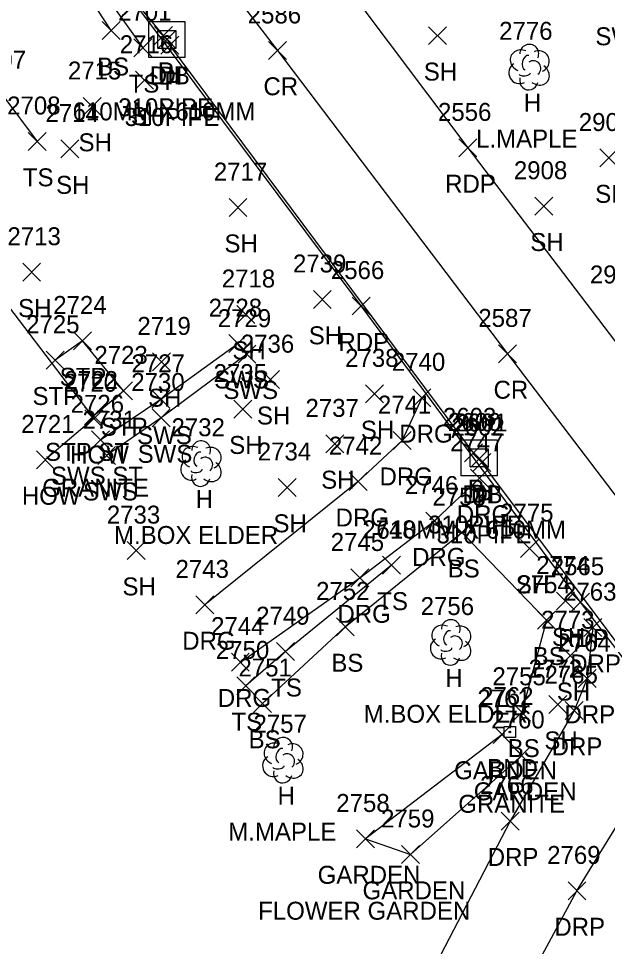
# Model space of a CAD drawing. Extents: x 1634209 to 1639641, y 608564 to 612258.
# Drawn here: x 1639264.6 to 1639330.2, y 610967 to 611070.4 of the extents above; entities that cross this region are included whole.
import ezdxf

# ---------------------------------------------------------------- set-up
doc = ezdxf.new("R2010")
doc.units = 0
for name, color, linetype in [('D_A', 7, 'Continuous'), ('D_C', 7, 'Continuous'), ('D_I', 7, 'Continuous'), ('D_TIC', 7, 'Continuous'), ('DCP', 7, 'Continuous'), ('DS', 7, 'Continuous'), ('L_A', 7, 'Continuous'), ('L_C', 7, 'Continuous'), ('L_I', 7, 'Continuous'), ('L_TIC', 7, 'Continuous'), ('LAPB', 7, 'Continuous'), ('LBC', 7, 'Continuous'), ('LBF', 7, 'Continuous'), ('LELB', 7, 'Continuous'), ('LTD', 7, 'Continuous'), ('M_A', 7, 'Continuous'), ('M_C', 7, 'Continuous'), ('M_I', 7, 'Continuous'), ('MHBP', 7, 'Continuous'), ('P_A', 7, 'Continuous'), ('P_I', 7, 'Continuous'), ('P_TIC', 7, 'Continuous'), ('PET', 7, 'Continuous'), ('PRC', 7, 'Continuous'), ('R_A', 7, 'Continuous'), ('R_I', 7, 'Continuous'), ('R_TIC', 7, 'Continuous'), ('RDG', 7, 'Continuous'), ('RDP', 7, 'Continuous'), ('RSW', 7, 'Continuous')]:
    doc.layers.add(name, color=color, linetype=linetype)

msp = doc.modelspace()

# ---------------------------------------------------------------- linework, layer by layer
at = {"layer": 'D_TIC'}
for points in [[(1639279.74, 611067.51), (1639281.74, 611069.51)], [(1639281.74, 611067.51), (1639279.74, 611069.51)], [(1639280.12, 611067.06), (1639282.12, 611069.06)], [(1639282.12, 611067.06), (1639280.12, 611069.06)], [(1639280.46, 611066.43), (1639282.46, 611068.43)], [(1639282.46, 611066.43), (1639280.46, 611068.43)], [(1639314.26, 611021.03), (1639316.26, 611023.03)], [(1639316.26, 611021.03), (1639314.26, 611023.03)], [(1639314.94, 611020.4), (1639316.94, 611022.4)], [(1639316.94, 611020.4), (1639314.94, 611022.4)], [(1639315.2, 611019.93), (1639317.2, 611021.93)], [(1639317.2, 611019.93), (1639315.2, 611021.93)]]:
    msp.add_lwpolyline(points, dxfattribs=at)
at = {"layer": 'DCP'}
for points in [[(1639280.74, 611068.51), (1639160.8, 611213.26)], [(1639315.26, 611022.03), (1639281.46, 611067.43)], [(1639346.24, 610980.85), (1639316.2, 611020.93)]]:
    msp.add_lwpolyline(points, dxfattribs=at)
at = {"layer": 'DS'}
for p, q in [((1639279.12, 611070.05), (1639283.12, 611070.05)), ((1639279.12, 611066.05), (1639279.12, 611070.05)), ((1639283.12, 611070.05), (1639283.12, 611066.05)), ((1639280.12, 611067.05), (1639280.12, 611069.05)), ((1639280.12, 611069.05), (1639282.12, 611069.05)), ((1639282.12, 611069.05), (1639282.12, 611067.05)), ((1639281.12, 611068.05), (1639281.12, 611068.05)), ((1639281.12, 611068.05), (1639281.12, 611068.05)), ((1639282.12, 611067.05), (1639280.12, 611067.05)), ((1639283.12, 611066.05), (1639279.12, 611066.05)), ((1639313.9, 611023.46), (1639317.9, 611023.46)), ((1639313.9, 611019.46), (1639313.9, 611023.46)), ((1639317.9, 611023.46), (1639317.9, 611019.46)), ((1639314.9, 611020.46), (1639314.9, 611022.46)), ((1639314.9, 611022.46), (1639316.9, 611022.46)), ((1639316.9, 611022.46), (1639316.9, 611020.46)), ((1639315.91, 611021.46), (1639315.91, 611021.46)), ((1639315.91, 611021.46), (1639315.91, 611021.46)), ((1639316.9, 611020.46), (1639314.9, 611020.46)), ((1639317.9, 611019.46), (1639313.9, 611019.46))]:
    msp.add_line(p, q, dxfattribs=at)
at = {"layer": 'L_TIC'}
for points in [[(1639273.91, 611068.05), (1639275.91, 611070.05)], [(1639275.91, 611068.05), (1639273.91, 611070.05)], [(1639310.26, 611067.49), (1639312.26, 611069.49)], [(1639312.26, 611067.49), (1639310.26, 611069.49)], [(1639277.46, 611066.15), (1639279.46, 611068.15)], [(1639279.46, 611066.15), (1639277.46, 611068.15)], [(1639277.63, 611062.53), (1639279.63, 611064.53)], [(1639279.63, 611062.53), (1639277.63, 611064.53)], [(1639271.8, 611059.61), (1639273.8, 611061.61)], [(1639273.8, 611059.61), (1639271.8, 611061.61)], [(1639265.68, 611055.71), (1639267.68, 611057.71)], [(1639267.68, 611055.71), (1639265.68, 611057.71)], [(1639269.31, 611054.87), (1639271.31, 611056.87)], [(1639271.31, 611054.87), (1639269.31, 611056.87)], [(1639329.34, 611053.87), (1639331.34, 611055.87)], [(1639331.34, 611053.87), (1639329.34, 611055.87)], [(1639288.05, 611048.35), (1639290.05, 611050.35)], [(1639290.05, 611048.35), (1639288.05, 611050.35)], [(1639322.11, 611048.5), (1639324.11, 611050.5)], [(1639324.11, 611048.5), (1639322.11, 611050.5)], [(1639265.07, 611041.15), (1639267.07, 611043.15)], [(1639267.07, 611041.15), (1639265.07, 611043.15)], [(1639297.44, 611038.11), (1639299.44, 611040.11)], [(1639299.44, 611038.11), (1639297.44, 611040.11)], [(1639288.93, 611036.44), (1639290.93, 611038.44)], [(1639290.93, 611036.44), (1639288.93, 611038.44)], [(1639270.73, 611033.49), (1639272.73, 611035.49)], [(1639272.73, 611033.49), (1639270.73, 611035.49)], [(1639267.7, 611031.35), (1639269.7, 611033.35)], [(1639269.7, 611031.35), (1639267.7, 611033.35)], [(1639279.54, 611031.16), (1639281.54, 611033.16)], [(1639281.54, 611031.16), (1639279.54, 611033.16)], [(1639291.67, 611029.18), (1639293.67, 611031.18)], [(1639293.67, 611029.18), (1639291.67, 611031.18)], [(1639275.31, 611027.93), (1639277.31, 611029.93)], [(1639277.31, 611027.93), (1639275.31, 611029.93)], [(1639303.24, 611027.6), (1639305.24, 611029.6)], [(1639305.24, 611027.6), (1639303.24, 611029.6)], [(1639288.59, 611025.9), (1639290.59, 611027.9)], [(1639290.59, 611025.9), (1639288.59, 611027.9)], [(1639271.97, 611025.13), (1639273.97, 611027.13)], [(1639273.97, 611025.13), (1639271.97, 611027.13)], [(1639271.98, 611024.83), (1639273.98, 611026.83)], [(1639273.98, 611024.83), (1639271.98, 611026.83)], [(1639298.82, 611022.03), (1639300.82, 611024.03)], [(1639300.82, 611022.03), (1639298.82, 611024.03)], [(1639266.59, 611020.24), (1639268.59, 611022.24)], [(1639268.59, 611020.24), (1639266.59, 611022.24)], [(1639293.51, 611017.17), (1639295.51, 611019.17)], [(1639295.51, 611017.17), (1639293.51, 611019.17)], [(1639312.96, 611012.14), (1639314.96, 611014.14)], [(1639314.96, 611012.14), (1639312.96, 611014.14)], [(1639276.7, 611010.14), (1639278.7, 611012.14)], [(1639278.7, 611010.14), (1639276.7, 611012.14)], [(1639320.5, 611010.37), (1639322.5, 611012.37)], [(1639322.5, 611010.37), (1639320.5, 611012.37)], [(1639305.15, 611008.5), (1639307.15, 611010.5)], [(1639307.15, 611008.5), (1639305.15, 611010.5)], [(1639324.52, 611004.52), (1639326.52, 611006.52)], [(1639326.52, 611004.52), (1639324.52, 611006.52)], [(1639300, 611001.64), (1639302, 611003.64)], [(1639302, 611001.64), (1639300, 611003.64)], [(1639322.42, 611002.39), (1639324.42, 611004.39)], [(1639324.42, 611002.39), (1639322.42, 611004.39)], [(1639293.34, 610998.88), (1639295.34, 611000.88)], [(1639295.34, 610998.88), (1639293.34, 611000.88)], [(1639325.06, 610998.43), (1639327.06, 611000.43)], [(1639327.06, 610998.43), (1639325.06, 611000.43)], [(1639288.92, 610995.07), (1639290.92, 610997.07)], [(1639290.92, 610995.07), (1639288.92, 610997.07)], [(1639290.79, 610993.11), (1639292.79, 610995.11)], [(1639292.79, 610993.11), (1639290.79, 610995.11)], [(1639323.68, 610992.99), (1639325.68, 610994.99)], [(1639325.68, 610992.99), (1639323.68, 610994.99)], [(1639319.64, 610992.13), (1639321.64, 610994.13)], [(1639321.64, 610992.13), (1639319.64, 610994.13)], [(1639317.45, 610989.66), (1639319.45, 610991.66)], [(1639319.45, 610989.66), (1639317.45, 610991.66)], [(1639319.64, 610987.32), (1639321.64, 610989.32)], [(1639321.64, 610987.32), (1639319.64, 610989.32)], [(1639302.25, 610978.02), (1639304.25, 610980.02)], [(1639304.25, 610978.02), (1639302.25, 610980.02)], [(1639307.25, 610976.29), (1639309.25, 610978.29)], [(1639309.25, 610976.29), (1639307.25, 610978.29)]]:
    msp.add_lwpolyline(points, dxfattribs=at)
at = {"layer": 'LAPB'}
for points in [[(1639303.25, 610979.02), (1639308.25, 610977.29), (1639320.64, 610988.32), (1639318.45, 610990.66)], [(1639318.45, 610990.66), (1639303.25, 610979.02)]]:
    msp.add_lwpolyline(points, dxfattribs=at)
at = {"layer": 'LBC'}
msp.add_lwpolyline([(1639253.26, 611038.19), (1639259.87, 611042.99), (1639272.98, 611025.83), (1639267.59, 611021.24)], dxfattribs=at)
at = {"layer": 'LBF'}
msp.add_lwpolyline([(1639272.97, 611026.13), (1639276.31, 611028.93), (1639271.73, 611034.49), (1639268.7, 611032.35)], dxfattribs=at)
at = {"layer": 'LELB'}
for points in [[(1639268.88, 611080.56), (1639278.46, 611067.15)], [(1639274.91, 611069.05), (1639268.28, 611079.25)], [(1639249.48, 611049.96), (1639262.84, 611061.82), (1639266.68, 611056.71)], [(1639291.79, 610994.11), (1639301, 611002.64), (1639313.96, 611013.14), (1639323.42, 611003.39), (1639320.64, 610993.13)], [(1639306.15, 611009.5), (1639294.34, 610999.88), (1639289.92, 610996.07)]]:
    msp.add_lwpolyline(points, dxfattribs=at)
at = {"layer": 'LTD'}
for p, q in [((1639321.45, 611065.03), (1639321.45, 611065.03)), ((1639321.45, 611065.03), (1639321.45, 611065.03)), ((1639284.9, 611020.87), (1639284.9, 611020.87)), ((1639284.9, 611020.87), (1639284.9, 611020.87)), ((1639312.71, 611000.95), (1639312.71, 611000.95)), ((1639312.71, 611000.95), (1639312.71, 611000.95)), ((1639294.03, 610987.84), (1639294.03, 610987.84)), ((1639294.03, 610987.84), (1639294.03, 610987.84))]:
    msp.add_line(p, q, dxfattribs=at)
for centre in [(1639321.49, 611066.47), (1639284.95, 611022.3), (1639312.75, 611002.39), (1639294.07, 610989.27)]:
    msp.add_arc(centre, 1.05, 335.5272, 180.9563, dxfattribs=at)
for centre, major_axis, ratio, start_param, end_param in [((1639320.66, 611065.7), (1.21, -0.51), 0.895232, 1.570796, 4.712389), ((1639322.49, 611065.62), (-1.14, -0.48), 0.949671, 1.570796, 4.712389), ((1639321.24, 611065.49), (-0.208, -0.792), 0.645439, 3.141593, 6.283185), ((1639321.95, 611064.87), (-0.5, 0.667), 0.989748, 3.141593, 6.283185), ((1639320.36, 611064.32), (0.58, -1.04), 0.959034, 3.141593, 6.283185), ((1639322.45, 611064.2), (-1.09, 0.79), 0.841452, 1.570796, 4.712389), ((1639321.45, 611063.53), (0.26, 1.06), 0.942809, 1.570796, 4.712389), ((1639320.99, 611064.28), (-0.625, -0.083), 0.423636, 0, 3.141593), ((1639284.11, 611021.53), (1.21, -0.51), 0.895232, 1.570796, 4.712389), ((1639284.69, 611021.32), (-0.208, -0.792), 0.645439, 3.141593, 6.283185), ((1639285.94, 611021.45), (-1.14, -0.48), 0.949671, 1.570796, 4.712389), ((1639283.82, 611020.16), (0.58, -1.04), 0.959034, 3.141593, 6.283185), ((1639285.4, 611020.7), (-0.5, 0.667), 0.989748, 3.141593, 6.283185), ((1639284.44, 611020.11), (-0.625, -0.083), 0.423636, 0, 3.141593), ((1639285.9, 611020.03), (-1.09, 0.79), 0.841452, 1.570796, 4.712389), ((1639284.9, 611019.37), (0.26, 1.06), 0.942809, 1.570796, 4.712389), ((1639311.92, 611001.62), (1.21, -0.51), 0.895232, 1.570796, 4.712389), ((1639313.75, 611001.54), (-1.14, -0.48), 0.949671, 1.570796, 4.712389), ((1639312.5, 611001.41), (-0.208, -0.792), 0.645439, 3.141593, 6.283185), ((1639313.21, 611000.79), (-0.5, 0.667), 0.989748, 3.141593, 6.283185), ((1639311.62, 611000.24), (0.58, -1.04), 0.959034, 3.141593, 6.283185), ((1639313.71, 611000.12), (-1.09, 0.79), 0.841452, 1.570796, 4.712389), ((1639312.71, 610999.45), (0.26, 1.06), 0.942809, 1.570796, 4.712389), ((1639312.25, 611000.2), (-0.625, -0.083), 0.423636, 0, 3.141593), ((1639293.24, 610988.5), (1.21, -0.51), 0.895232, 1.570796, 4.712389), ((1639293.82, 610988.3), (-0.208, -0.792), 0.645439, 3.141593, 6.283185), ((1639295.07, 610988.42), (-1.14, -0.48), 0.949671, 1.570796, 4.712389), ((1639292.94, 610987.13), (0.58, -1.04), 0.959034, 3.141593, 6.283185), ((1639294.53, 610987.67), (-0.5, 0.667), 0.989748, 3.141593, 6.283185), ((1639293.57, 610987.09), (-0.625, -0.083), 0.423636, 0, 3.141593), ((1639295.03, 610987), (-1.09, 0.79), 0.841452, 1.570796, 4.712389), ((1639294.03, 610986.34), (0.26, 1.06), 0.942809, 1.570796, 4.712389)]:
    msp.add_ellipse(centre, major_axis=major_axis, ratio=ratio, start_param=start_param, end_param=end_param, dxfattribs=at)
at = {"layer": 'MHBP'}
msp.add_lwpolyline([(1639318.69, 610991.55), (1639319.94, 610991.55), (1639319.94, 610990.3), (1639318.69, 610990.3)], close=True, dxfattribs=at)
msp.add_circle((1639319.32, 610990.93), 0.0833, dxfattribs=at)
at = {"layer": 'P_TIC'}
for points in [[(1639292.45, 611065.85), (1639294.45, 611067.85)], [(1639294.45, 611065.85), (1639292.45, 611067.85)], [(1639313.63, 611055), (1639315.63, 611057)], [(1639315.63, 611055), (1639313.63, 611057)], [(1639301.75, 611037.38), (1639303.75, 611039.38)], [(1639303.75, 611037.38), (1639301.75, 611039.38)], [(1639318.07, 611032.05), (1639320.07, 611034.05)], [(1639320.07, 611032.05), (1639318.07, 611034.05)], [(1639326.19, 611004.39), (1639328.19, 611006.39)], [(1639328.19, 611004.39), (1639326.19, 611006.39)]]:
    msp.add_lwpolyline(points, dxfattribs=at)
at = {"layer": 'PET'}
for points in [[(1639410.83, 610892.36), (1639390.46, 610919.54), (1639371.8, 610946.36), (1639349.88, 610975.7), (1639327.19, 611005.39), (1639302.75, 611038.38), (1639275.03, 611075.51), (1639248.83, 611108.82), (1639223.63, 611142.44), (1639205.3, 611166.28), (1639182.18, 611194.12), (1639165.68, 611212.04), (1639150.22, 611225.99), (1639136.4, 611234.04), (1639135.28, 611232.53), (1639130.92, 611235.28), (1639127.56, 611237.66), (1639124.14, 611238.64)], [(1639231.62, 611167.79), (1639256.2, 611134.45), (1639283.54, 611097.44), (1639314.63, 611056), (1639346.72, 611013.84), (1639378.41, 610971.72), (1639408.01, 610931), (1639426.87, 610904.61)]]:
    msp.add_lwpolyline(points, dxfattribs=at)
at = {"layer": 'PRC'}
msp.add_lwpolyline([(1639145.03, 611260.3), (1639159.74, 611243.63), (1639188.7, 611206.44), (1639218.55, 611167.28), (1639245.48, 611130.83), (1639271.83, 611094.92), (1639293.45, 611066.85), (1639319.07, 611033.05), (1639349.49, 610993.07), (1639374.14, 610959.6), (1639396.77, 610928.59), (1639419.08, 610897.87)], dxfattribs=at)
at = {"layer": 'R_TIC'}
for points in [[(1639288.04, 611033.19), (1639290.04, 611035.19)], [(1639290.04, 611033.19), (1639288.04, 611035.19)], [(1639289.05, 611032.02), (1639291.05, 611034.02)], [(1639291.05, 611032.02), (1639289.05, 611034.02)], [(1639279.44, 611026.99), (1639281.44, 611028.99)], [(1639281.44, 611026.99), (1639279.44, 611028.99)], [(1639308.53, 611027.16), (1639310.53, 611029.16)], [(1639310.53, 611027.16), (1639308.53, 611029.16)], [(1639279.5, 611024.91), (1639281.5, 611026.91)], [(1639281.5, 611024.91), (1639279.5, 611026.91)], [(1639272.72, 611022.48), (1639274.72, 611024.48)], [(1639274.72, 611022.48), (1639272.72, 611024.48)], [(1639306.32, 611022.39), (1639308.32, 611024.39)], [(1639308.32, 611022.39), (1639306.32, 611024.39)], [(1639273.42, 611020.72), (1639275.42, 611022.72)], [(1639275.42, 611020.72), (1639273.42, 611022.72)], [(1639314.93, 611018.19), (1639316.93, 611020.19)], [(1639316.93, 611018.19), (1639314.93, 611020.19)], [(1639301.43, 611017.82), (1639303.43, 611019.82)], [(1639303.43, 611017.82), (1639301.43, 611019.82)], [(1639309.95, 611013.43), (1639311.95, 611015.43)], [(1639311.95, 611013.43), (1639309.95, 611015.43)], [(1639301.63, 611007.09), (1639303.63, 611009.09)], [(1639303.63, 611007.09), (1639301.63, 611009.09)], [(1639284.35, 611004.09), (1639286.35, 611006.09)], [(1639286.35, 611004.09), (1639284.35, 611006.09)], [(1639327.56, 611001.56), (1639329.56, 611003.56)], [(1639329.56, 611001.56), (1639327.56, 611003.56)], [(1639288.31, 610997.72), (1639290.31, 610999.72)], [(1639290.31, 610997.72), (1639288.31, 610999.72)], [(1639326.92, 610995.89), (1639328.92, 610997.89)], [(1639328.92, 610995.89), (1639326.92, 610997.89)], [(1639325.49, 610992.32), (1639327.49, 610994.32)], [(1639327.49, 610992.32), (1639325.49, 610994.32)], [(1639318.37, 610980.01), (1639320.37, 610982.01)], [(1639320.37, 610980.01), (1639318.37, 610982.01)], [(1639325.8, 610972.23), (1639327.8, 610974.23)], [(1639327.8, 610972.23), (1639325.8, 610974.23)]]:
    msp.add_lwpolyline(points, dxfattribs=at)
at = {"layer": 'RDG'}
for points in [[(1639309.53, 611028.16), (1639307.32, 611023.39), (1639302.43, 611018.82), (1639285.35, 611005.09)], [(1639289.31, 610998.72), (1639302.63, 611008.09), (1639310.95, 611014.43), (1639315.93, 611019.19)]]:
    msp.add_lwpolyline(points, dxfattribs=at)
at = {"layer": 'RDP'}
for points in [[(1639328.56, 611002.56), (1639327.92, 610996.89), (1639326.49, 610993.32), (1639319.37, 610981.01), (1639309.16, 610961.36)], [(1639317.57, 610956.14), (1639326.8, 610973.23), (1639334.72, 610986.17), (1639338.64, 610988.48)]]:
    msp.add_lwpolyline(points, dxfattribs=at)
at = {"layer": 'RSW'}
msp.add_lwpolyline([(1639273.72, 611023.48), (1639280.44, 611027.99), (1639289.04, 611034.19), (1639290.05, 611033.02), (1639280.5, 611025.91), (1639274.42, 611021.72)], dxfattribs=at)

# ---------------------------------------------------------------- texts
at = {"layer": 'D_A'}
for s, p in [('P', (1639280.12, 611063.51)), ('DIB', (1639279.22, 611063.06)), ('DI', (1639280.18, 611063.05)), ('P', (1639280.84, 611062.43)), ('P', (1639314.64, 611017.03)), ('DIB', (1639314.04, 611016.4)), ('DI', (1639314.96, 611016.46)), ('P', (1639315.58, 611015.93))]:
    msp.add_text(s, height=2, dxfattribs=at).set_placement(p)
at = {"layer": 'D_C'}
for s, p in [('310PIPE', (1639275.71, 611059.51)), ('610MM X610MM', (1639270.63, 611059.05)), ('310PIPE', (1639276.42, 611058.43)), ('310PIPE', (1639310.22, 611013.03)), ('610MM X 610MM', (1639304.46, 611012.46)), ('310PIPE', (1639311.16, 611011.93))]:
    msp.add_text(s, height=2, dxfattribs=at).set_placement(p)
at = {"layer": 'D_I'}
for s, p in [('2603', (1639311.87, 611025.03)), ('2600', (1639312.43, 611024.46)), ('2601', (1639313.12, 611024.4)), ('2602', (1639312.81, 611023.93))]:
    msp.add_text(s, height=2, dxfattribs=at).set_placement(p)
at = {"layer": 'L_A'}
for s, p in [('BS', (1639273.35, 611064.05)), ('SH', (1639309.74, 611063.49)), ('TS', (1639276.87, 611062.15)), ('H', (1639320.88, 611060.03)), ('SH', (1639277.12, 611058.53)), ('SH', (1639271.29, 611055.61)), ('TS', (1639265.09, 611051.71)), ('SH', (1639268.79, 611050.87)), ('SH', (1639328.83, 611049.87)), ('SH', (1639287.54, 611044.35)), ('SH', (1639321.6, 611044.5)), ('SH', (1639264.56, 611037.15)), ('SH', (1639296.93, 611034.11)), ('SH', (1639288.42, 611032.44)), ('STP', (1639269.19, 611029.49)), ('STP', (1639266.16, 611027.35)), ('SH', (1639279.03, 611027.16)), ('SH', (1639291.16, 611025.18)), ('STP', (1639273.77, 611023.93)), ('SH', (1639302.73, 611023.6)), ('STP ST', (1639267.56, 611021.13)), ('SH', (1639288.07, 611021.9)), ('HOW', (1639270.36, 611020.83)), ('SH', (1639298.31, 611018.03)), ('HOW', (1639264.98, 611016.24)), ('H', (1639284.33, 611015.87)), ('SH', (1639293, 611013.17)), ('BS', (1639312.4, 611008.14)), ('SH', (1639276.18, 611006.14)), ('SH', (1639319.99, 611006.37)), ('TS', (1639304.56, 611004.5)), ('SH', (1639324.01, 611000.52)), ('BS', (1639321.86, 610998.39)), ('BS', (1639299.44, 610997.64)), ('H', (1639312.14, 610995.95)), ('TS', (1639292.75, 610994.88)), ('SH', (1639324.55, 610994.43)), ('TS', (1639288.33, 610991.07)), ('BS', (1639290.23, 610989.11)), ('BS', (1639319.08, 610988.13)), ('SH', (1639323.17, 610988.99)), ('GARDEN', (1639313.12, 610985.66)), ('GARDEN', (1639315.31, 610983.32)), ('H', (1639293.46, 610982.84)), ('GARDEN', (1639297.92, 610974.02)), ('GARDEN', (1639302.92, 610972.29))]:
    msp.add_text(s, height=2, dxfattribs=at).set_placement(p)
at = {"layer": 'L_C'}
for s, p in [('L.MAPLE', (1639315.56, 611056.03)), ('GRANITE', (1639267.24, 611017.13)), ('M.BOX ELDER', (1639275.24, 611011.87)), ('M.BOX ELDER', (1639303.05, 610991.95)), ('M.MAPLE', (1639287.96, 610978.84)), ('FLOWER GARDEN', (1639291.29, 610970.02))]:
    msp.add_text(s, height=2, dxfattribs=at).set_placement(p)
at = {"layer": 'L_I'}
for s, p in [('2701', (1639275.69, 611070.15)), ('2776', (1639318.13, 611068.03)), ('2716', (1639275.88, 611066.53)), ('2707', (1639259.5, 611064.82)), ('2715', (1639270.11, 611063.61)), ('2708', (1639263.34, 611059.71)), ('2714', (1639267.61, 611058.87)), ('2907', (1639327, 611057.87)), ('2717', (1639286.36, 611052.35)), ('2908', (1639319.77, 611052.5)), ('2713', (1639263.37, 611045.15)), ('2739', (1639295.17, 611042.11)), ('2909', (1639328.24, 611040.89)), ('2718', (1639287.24, 611040.44)), ('2724', (1639268.47, 611037.49)), ('2725', (1639265.45, 611035.35)), ('2719', (1639277.84, 611035.16)), ('2736', (1639289.36, 611033.18)), ('2723', (1639273.05, 611031.93)), ('2738', (1639300.98, 611031.6)), ('2735', (1639286.33, 611029.9)), ('2720', (1639269.63, 611028.83)), ('2722', (1639269.71, 611029.13)), ('2737', (1639296.56, 611026.03)), ('2721', (1639264.9, 611024.24)), ('2732', (1639281.64, 611023.87)), ('2734', (1639291.25, 611021.17)), ('2753', (1639310.7, 611016.14)), ('2733', (1639274.44, 611014.14)), ('2775', (1639318.24, 611014.37)), ('2748', (1639302.89, 611012.5)), ('2774', (1639322.26, 611008.52)), ('2752', (1639297.74, 611005.64)), ('2754', (1639320.16, 611006.39)), ('2756', (1639309.39, 611003.95)), ('2749', (1639291.07, 611002.88)), ('2773', (1639322.8, 611002.43)), ('2750', (1639286.58, 610999.07)), ('2751', (1639289.1, 610997.11)), ('2772', (1639321.42, 610996.99)), ('2755', (1639317.38, 610996.13)), ('2761', (1639315.71, 610993.66)), ('2760', (1639317.25, 610991.32)), ('2757', (1639290.77, 610990.84)), ('2758', (1639299.99, 610982.02)), ('2759', (1639304.98, 610980.29))]:
    msp.add_text(s, height=2, dxfattribs=at).set_placement(p)
at = {"layer": 'M_A'}
msp.add_text('BND', height=2, dxfattribs=at).set_placement((1639316.8, 610985.93))
at = {"layer": 'M_C'}
msp.add_text('GRANITE', height=2, dxfattribs=at).set_placement((1639313.58, 610981.93))
at = {"layer": 'M_I'}
msp.add_text('2762', height=2, dxfattribs=at).set_placement((1639316.01, 610993.93))
at = {"layer": 'P_A'}
for s, p in [('CR', (1639291.88, 611061.85)), ('RDP', (1639312.12, 611051)), ('RDP', (1639300.24, 611033.38)), ('CR', (1639317.51, 611028.05)), ('RDP', (1639324.68, 611000.39))]:
    msp.add_text(s, height=2, dxfattribs=at).set_placement(p)
at = {"layer": 'P_I'}
for s, p in [('2586', (1639290.13, 611069.85)), ('2556', (1639311.32, 611059)), ('2566', (1639299.39, 611041.38)), ('2587', (1639315.81, 611036.05)), ('2565', (1639323.88, 611008.39))]:
    msp.add_text(s, height=2, dxfattribs=at).set_placement(p)
at = {"layer": 'R_A'}
for s, p in [('SWC', (1639328.85, 611067.42)), ('SWS', (1639286.41, 611029.19)), ('SWS', (1639287.42, 611028.02)), ('DRG', (1639307.01, 611023.16)), ('SWS', (1639277.81, 611022.99)), ('SWS', (1639277.87, 611020.91)), ('SWS ST', (1639268.22, 611018.48)), ('DRG', (1639304.81, 611018.39)), ('SWS', (1639271.79, 611016.72)), ('DRG', (1639299.92, 611013.82)), ('DRG', (1639313.42, 611014.19)), ('DRG', (1639308.44, 611009.43)), ('DRG', (1639300.12, 611003.09)), ('DRG', (1639282.84, 611000.09)), ('DRP', (1639326.05, 610997.56)), ('DRG', (1639286.8, 610993.72)), ('DRP', (1639325.41, 610991.89)), ('DRP', (1639323.98, 610988.32)), ('DRP', (1639316.86, 610976.01)), ('DRP', (1639324.28, 610968.23))]:
    msp.add_text(s, height=2, dxfattribs=at).set_placement(p)
at = {"layer": 'R_I'}
for s, p in [('2728', (1639285.78, 611037.19)), ('2729', (1639286.79, 611036.02)), ('2727', (1639277.18, 611030.99)), ('2740', (1639306.18, 611031.16)), ('2730', (1639277.16, 611028.91)), ('2726', (1639270.41, 611026.48)), ('2741', (1639304.63, 611026.39)), ('2731', (1639271.73, 611024.72)), ('2747', (1639312.67, 611022.19)), ('2742', (1639299.17, 611021.82)), ('2746', (1639307.63, 611017.43)), ('2745', (1639299.37, 611011.09)), ('2743', (1639282.09, 611008.09)), ('2763', (1639325.25, 611005.56)), ('2744', (1639286.05, 611001.72)), ('2764', (1639324.61, 610999.89)), ('2765', (1639323.18, 610996.32)), ('2766', (1639316.01, 610984.01)), ('2769', (1639323.48, 610976.23))]:
    msp.add_text(s, height=2, dxfattribs=at).set_placement(p)

doc.saveas('drawing.dxf')
